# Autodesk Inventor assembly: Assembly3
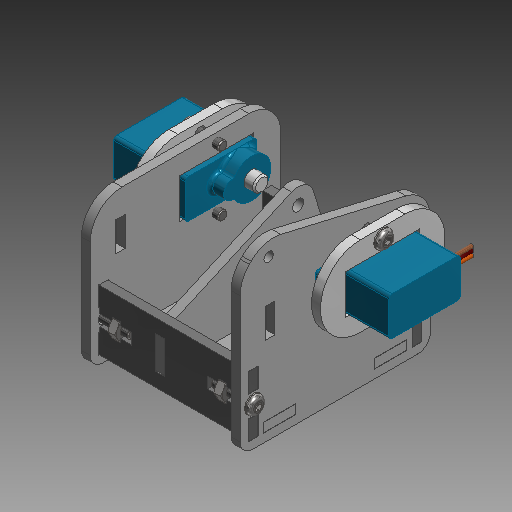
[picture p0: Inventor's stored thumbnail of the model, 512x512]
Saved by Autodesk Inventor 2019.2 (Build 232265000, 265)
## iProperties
Part Number: Assembly3
Document SubType Name: Assembly
Designer: richard.girt
Mass: 55.9502 g
Surface Area: 353.65 cm^2
Volume: 44.9491 cm^3
Density: 1.24475 g/cm^3
Author: richard.girt
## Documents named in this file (15)
- C:\Users\richard.girt\Desktop\2 Axis robotic arm\Assembly3.iam
- C:\Users\richard.girt\Desktop\2 Axis robotic arm\Part1.ipt
- C:\Users\richard.girt\Desktop\2 Axis robotic arm\Part9.ipt
- C:\Users\richard.girt\Desktop\2 Axis robotic arm\SG90.ipt
- C:\Users\richard.girt\Desktop\2 Axis robotic arm\Part11.ipt
- C:\Users\richard.girt\Desktop\2 Axis robotic arm\Part13.ipt
- C:\Users\richard.girt\Desktop\2 Axis robotic arm\Part12.ipt
- C:\Users\richard.girt\Desktop\2 Axis robotic arm\SG90Horn2.ipt
- C:\Users\richard.girt\Desktop\2 Axis robotic arm\ANSI B18.6.5M - M2.5x0.45 x 4(38).ipt
- C:\Users\richard.girt\Desktop\2 Axis robotic arm\ANSI B18.6.5M - M2.5x0.45 x 8(38).ipt
- ANSI B18.6.5M - M2.5x0.45 x 8(38).ipt
- C:\Users\richard.girt\Desktop\2 Axis robotic arm\Part15.ipt
- C:\Users\richard.girt\Desktop\2 Axis robotic arm\ANSI B 18.2.4.1 M - M3 x 0.5Style 1.ipt
- C:\Users\richard.girt\Desktop\2 Axis robotic arm\ANSI B18.3.4M - M3 x 0.5 x 12(1).ipt
- C:\Users\richard.girt\Desktop\2 Axis robotic arm\ANSI B18.3.4M - M3 x 0.5 x 8(1).ipt
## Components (26 placed, 13 different names)
1. Part12:1 — Mate:1, Mate:2, Flush:1, Flush:2, Flush:3, Flush:4, Flush:9, Flush:12, Rigid:1, Mate:16, Mate:17, Flush:16
2. SG90:1 — Mate:3, Mate:4, Mate:5, Mate:8
3. Part11:1 — Mate:6, Mate:7, Mate:8, Flush:2, Flush:3, Flush:4, Flush:7, Flush:8, Flush:10, Flush:11, Flush:14, Flush:15, Rigid:21, Rigid:22, Rigid:23, Rigid:24
4. Part1:2 — Mate:3, Mate:4, Mate:5, Mate:6, Mate:7, Rigid:13, Rigid:16
5. Part13:1 — Flush:7, Flush:8, Flush:9, Flush:13
6. Part13:2 — Flush:10, Flush:11, Flush:12
7. SG90:2 — Mate:13
8. Part1:3 — Mate:14, Mate:15, Rigid:14, Rigid:15
9. Part9:1 — Flush:13, Flush:14, Flush:15, Mate:13, Mate:14, Mate:15, Rigid:17, Rigid:18, Rigid:19, Rigid:20
10. SG90Horn2:1 — Rigid:1, Rigid:2, Rigid:3, Rigid:4
11. ANSI B18.6.5M - M2.5x0.45 x 4(38):1 — Rigid:2
12. ANSI B18.6.5M - M2.5x0.45 x 8(38):1 — Rigid:3
13. ANSI B18.6.5M - M2.5x0.45 x 8(38):2 — Rigid:4
14. Part15:1 — Mate:16, Mate:17, Flush:16
15. ANSI B 18.2.4.1 M - M3 x 0.5Style 1:1 — Rigid:20
16. ANSI B 18.2.4.1 M - M3 x 0.5Style 1:2 — Rigid:24
17. ANSI B 18.2.4.1 M - M3 x 0.5Style 1:3 — Rigid:21
18. ANSI B 18.2.4.1 M - M3 x 0.5Style 1:4 — Rigid:19
19. ANSI B18.3.4M - M3 x 0.5 x 12(1):1 — Rigid:23
20. ANSI B18.3.4M - M3 x 0.5 x 12(1):2 — Rigid:22
21. ANSI B18.3.4M - M3 x 0.5 x 12(1):3 — Rigid:17
22. ANSI B18.3.4M - M3 x 0.5 x 12(1):4 — Rigid:18
23. ANSI B18.3.4M - M3 x 0.5 x 8(1):1 — Rigid:13
24. ANSI B18.3.4M - M3 x 0.5 x 8(1):2 — Rigid:16
25. ANSI B18.3.4M - M3 x 0.5 x 8(1):3 — Rigid:14
26. ANSI B18.3.4M - M3 x 0.5 x 8(1):4 — Rigid:15
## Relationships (43: WeldJoint 16, Flush 14, Mate 13)
- Mate:1: Part12:1
- Mate:2: Part12:1
- Flush:1: Part12:1
- Mate:3: SG90:1 ↔ Part1:2
- Mate:4: SG90:1 ↔ Part1:2
- Mate:5: SG90:1 ↔ Part1:2
- Mate:6: Part11:1 ↔ Part1:2
- Mate:7: Part11:1 ↔ Part1:2
- Mate:8: SG90:1 ↔ Part11:1
- Flush:2: Part12:1 ↔ Part11:1
- Flush:3: Part12:1 ↔ Part11:1
- Flush:4: Part12:1 ↔ Part11:1
- Flush:7: Part11:1 ↔ Part13:1
- Flush:8: Part11:1 ↔ Part13:1
- Flush:9: Part12:1 ↔ Part13:1
- Flush:10: Part11:1 ↔ Part13:2
- Flush:11: Part11:1 ↔ Part13:2
- Flush:12: Part12:1 ↔ Part13:2
- Flush:13: Part13:1 ↔ Part9:1
- Flush:14: Part11:1 ↔ Part9:1
- Flush:15: Part11:1 ↔ Part9:1
- Mate:13: SG90:2 ↔ Part9:1
- Mate:14: Part1:3 ↔ Part9:1
- Mate:15: Part1:3 ↔ Part9:1
- Rigid:1 [WeldJoint]: Part12:1 ↔ SG90Horn2:1
- Rigid:2 [WeldJoint]: SG90Horn2:1 ↔ ANSI B18.6.5M - M2.5x0.45 x 4(38):1
- Rigid:3 [WeldJoint]: SG90Horn2:1 ↔ ANSI B18.6.5M - M2.5x0.45 x 8(38):1
- Rigid:4 [WeldJoint]: SG90Horn2:1 ↔ ANSI B18.6.5M - M2.5x0.45 x 8(38):2
- Mate:16: Part12:1 ↔ Part15:1
- Mate:17: Part12:1 ↔ Part15:1
- Flush:16: Part12:1 ↔ Part15:1
- Rigid:13 [WeldJoint]: Part1:2 ↔ ANSI B18.3.4M - M3 x 0.5 x 8(1):1
- Rigid:14 [WeldJoint]: Part1:3 ↔ ANSI B18.3.4M - M3 x 0.5 x 8(1):3
- Rigid:15 [WeldJoint]: Part1:3 ↔ ANSI B18.3.4M - M3 x 0.5 x 8(1):4
- Rigid:16 [WeldJoint]: Part1:2 ↔ ANSI B18.3.4M - M3 x 0.5 x 8(1):2
- Rigid:17 [WeldJoint]: Part9:1 ↔ ANSI B18.3.4M - M3 x 0.5 x 12(1):3
- Rigid:18 [WeldJoint]: Part9:1 ↔ ANSI B18.3.4M - M3 x 0.5 x 12(1):4
- Rigid:19 [WeldJoint]: Part9:1 ↔ ANSI B 18.2.4.1 M - M3 x 0.5Style 1:4
- Rigid:20 [WeldJoint]: Part9:1 ↔ ANSI B 18.2.4.1 M - M3 x 0.5Style 1:1
- Rigid:21 [WeldJoint]: Part11:1 ↔ ANSI B 18.2.4.1 M - M3 x 0.5Style 1:3
- Rigid:22 [WeldJoint]: Part11:1 ↔ ANSI B18.3.4M - M3 x 0.5 x 12(1):2
- Rigid:23 [WeldJoint]: Part11:1 ↔ ANSI B18.3.4M - M3 x 0.5 x 12(1):1
- Rigid:24 [WeldJoint]: Part11:1 ↔ ANSI B 18.2.4.1 M - M3 x 0.5Style 1:2
## Named parameters: d22_d6 = 0, d23_d3 = 0, d24_d4 = 0
